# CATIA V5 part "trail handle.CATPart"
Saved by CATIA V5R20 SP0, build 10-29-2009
Part number: th
Bounding box of the stored display mesh (mm): x 0 to 870, y 0 to 164.07, z 0 to 600
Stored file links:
  C:\Users\HP\Downloads\Catia Project\Catia Project\trail handle.CATPart
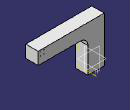
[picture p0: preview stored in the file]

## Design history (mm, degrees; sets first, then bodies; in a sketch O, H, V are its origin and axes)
Body1 (main body)
  Sketch1 on xy-plane, origin (0, 0, 0), H (1, 0, 0), V (0, 1, 0)
    line L1 (0, 0) -> (170, 0)
    line L2 (170, 0) -> (170, 164.07)
    line L3 (170, 164.07) -> (0, 164.07)
    line L4 (0, 164.07) -> (0, 0)
    length L1 = 170
    length L4 = 164.07
    horizontal: L1 H, L3 H
    vertical: L2 V, L4 V
  Pad1: profile Sketch1, direction (0, 0, 1), length 600
  Sketch2 on face of Pad1 from Sketch1.L2, origin (170, 0, 0), H (0, 1, 0), V (0, 0, 1)
    line L1 (0, 600) -> (164.07, 600)
    line L2 (164.07, 600) -> (164.07, 438.5)
    line L3 (164.07, 438.5) -> (0, 438.5)
    line L4 (0, 438.5) -> (0, 600)
    reference projected line E1 (0, 600) -> (164.07, 600) from edge [face of Pad1 from Sketch1.L2 | end face of Pad1]
    reference projected line E2 (0, 0) -> (0, 600) from edge [face of Pad1 from Sketch1.L2 | face of Pad1 from Sketch1.L1]
    reference projected line E3 (164.07, 0) -> (164.07, 600) from edge [face of Pad1 from Sketch1.L3 | face of Pad1 from Sketch1.L2]
    length L2 = 161.5
    horizontal: L1 H, L3 H
    vertical: L2 V, L4 V
    coincidence: L1 E1, L4 E2, L2 E3
  Sketch3 on face of Pad1 from Sketch1.L2, origin (170, 0, 0), H (0, 1, 0), V (0, 0, 1)
  Pad2: profile Sketch2, direction (1, 0, 0), length 700
  Sketch4 on face of Pad1 from Sketch1.L2, origin (170, 0, 0), H (0, 1, 0), V (0, 0, 1)
    line L1 (0, 438.5) -> (164.07, 438.5)
    line L2 (164.07, 438.5) -> (164.07, 0)
    line L3 (164.07, 0) -> (0, 0)
    line L4 (0, 0) -> (0, 438.5)
    reference projected line E1 (164.07, 0) -> (164.07, 600) from edge [face of Pad2 | face of Pad1 from Sketch1.L2]
    reference projected line E2 (0, 0) -> (0, 600) from edge [face of Pad1 from Sketch1.L2 | face of Pad2]
    reference projected line E3 (0, 0) -> (164.07, 0) from edge [start face of Pad1 | face of Pad1 from Sketch1.L2]
    reference projected line E4 (0, 438.5) -> (164.07, 438.5) from edge [face of Pad2 from Sketch2.L3 | end face of Pad2]
    horizontal: L1 H, L3 H
    vertical: L2 V, L4 V
    coincidence: L2 E1, E2 L4, L3 E3, L1 E4
  Pad3: profile Sketch4, direction (1, 0, 0), length 45
  Sketch5 on face of Pad3, origin (0, 164.07, 0), H (-1, 0, 0), V (0, 0, 1)
    arc A1 centre (-315, 338.5) radius 100 from (-215, 338.5) to (-315, 438.5) ccw
    reference projected line E1 (-170, 438.5) -> (-870, 438.5) from edge [face of Pad3 | face of Pad2 from Sketch2.L3]
    reference projected line E2 (-215, 0) -> (-215, 438.5) from edge [face of Pad3 | end face of Pad3]
    line L1 (-315, 438.5) -> (-215, 438.5)
    line L2 (-215, 438.5) -> (-215, 338.5)
    reference projected line E3 (-215, 0) -> (-215, 438.5) from edge [face of Pad3 | end face of Pad3]
    reference projected line E4 (-170, 438.5) -> (-870, 438.5) from edge [face of Pad3 | face of Pad2 from Sketch2.L3]
    radius A1 = 100
    tangency: A1 E1, A1 E2, L1 A1, L2 A1
    coincidence: L2 E3, L1 E4
  Pad4: profile Sketch5, direction (0, -1, 0), length 164.07
  Sketch6 on face of Pad4, origin (0, 0, 0), H (1, 0, 0), V (0, 0, 1)
    circle A1 centre (792.83, 579.85) radius 4
    point P1 (792.83, 579.85)
    circle A2 centre (840.98, 579.85) radius 4
    point P2 (840.98, 579.85)
    circle A3 centre (840.98, 531.7) radius 4
    point P3 (840.98, 531.7)
    circle A4 centre (792.83, 531.7) radius 4
    point P4 (792.83, 531.7)
    reference projected line E1 (870, 600) -> (870, 438.5) from edge [face of Pad4 | end face of Pad2]
    reference projected line E2 (870, 600) -> (870, 438.5) from edge [face of Pad4 | end face of Pad2]
    reference projected line E3 (0, 600) -> (170, 600) from edge [face of Pad4 | face of Pad2]
    reference projected line E4 (0, 600) -> (170, 600) from edge [face of Pad4 | face of Pad2]
    radius A1 = 4
    radius A2 = 4
    radius A3 = 4
    radius A4 = 4
    distance P2 E1 = 29.02
    distance P3 E2 = 29.02
    distance P2 P3 = 48.15
    distance P3 P4 = 48.15
    distance P1 E3 = 20.15
    distance P2 E4 = 20.15
    distance P2 P1 = 48.15
  Pocket1: profile Sketch6, direction (0, 1, 0), through (limit type 3)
